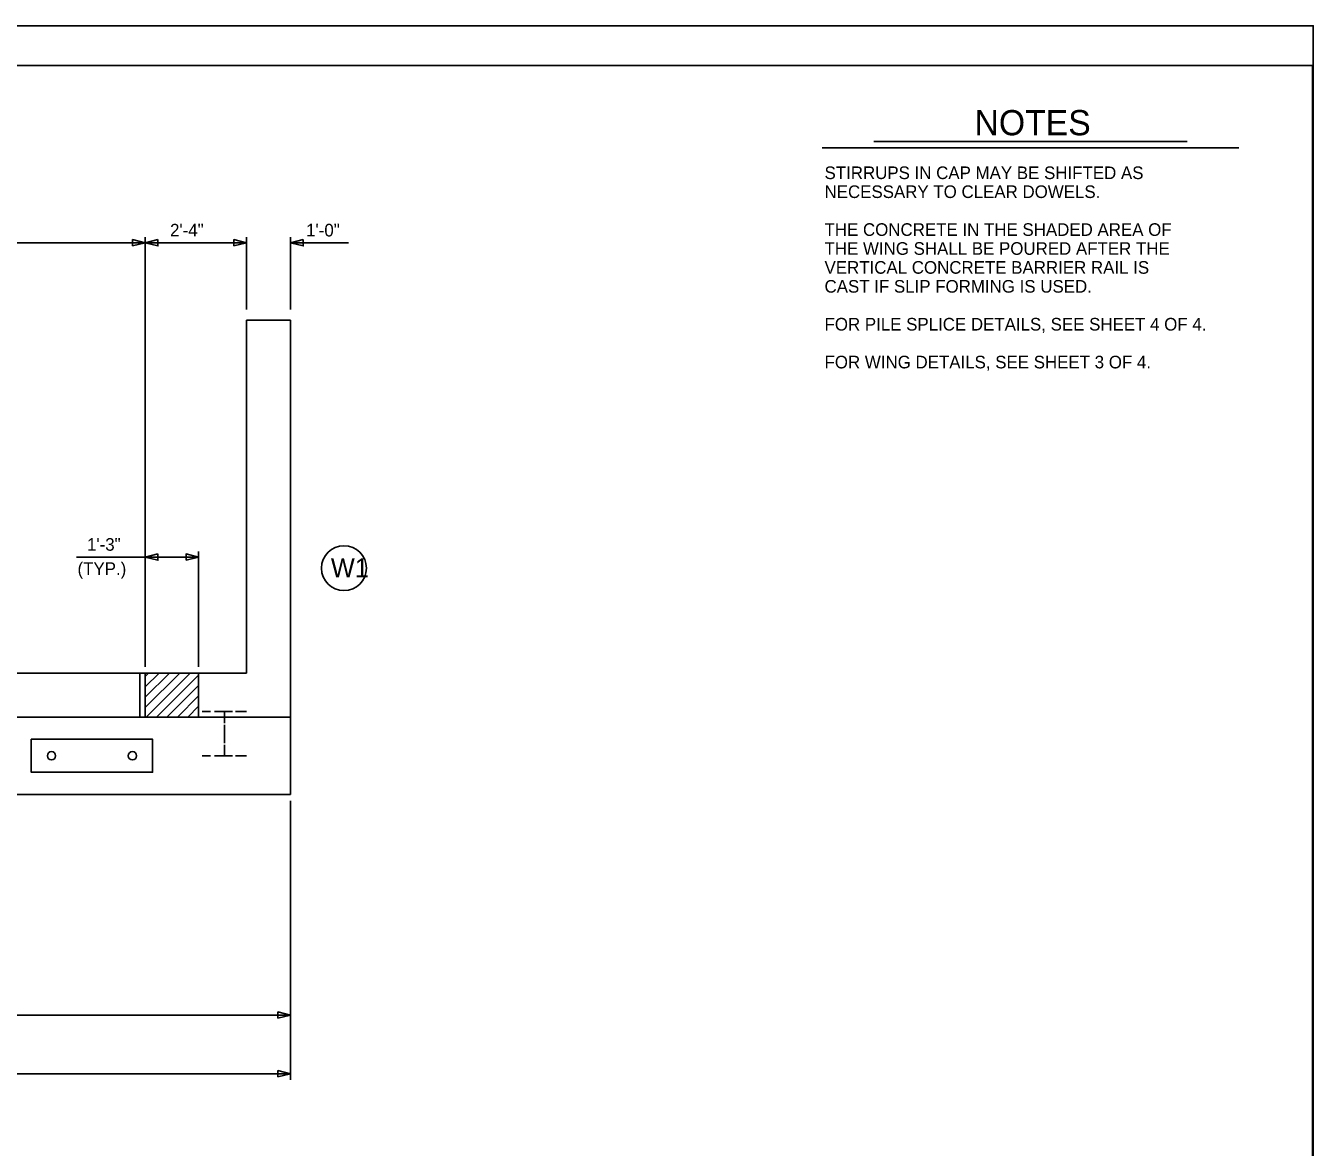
# Model space of a CAD drawing. Extents: x -41 to 251, y -169 to 237.
# Drawn here: x 132.26 to 161.43, y -25.59 to -0.17 of the extents above; entities that cross this region are included whole.
import ezdxf

# ---------------------------------------------------------------- set-up
doc = ezdxf.new("R2010")
doc.units = 0
for name, color, linetype in [('Arrowhead Terminators', 7, 'Continuous'), ('Dimension Lines', 7, 'Continuous'), ('Mis Object Lines', 7, 'Continuous'), ('Miscellaneous Lines', 7, 'Continuous'), ('Plan Sheet CELL', 7, 'Continuous'), ('Plot Shape CELL', 7, 'Continuous'), ('Rebar Lines', 7, 'Continuous'), ('Subtitle Text', 7, 'Continuous'), ('Text', 7, 'Continuous'), ('Title Text', 7, 'Continuous')]:
    doc.layers.add(name, color=color, linetype=linetype)

msp = doc.modelspace()

# ---------------------------------------------------------------- linework, layer by layer
at = {"layer": 'Arrowhead Terminators'}
for points in [[(134.685, -5.163), (134.971, -5.092), (134.685, -5.02)], [(135.257, -5.02), (134.971, -5.092), (135.257, -5.163)], [(136.977, -5.163), (137.263, -5.092), (136.977, -5.02)], [(138.549, -5.02), (138.263, -5.092), (138.549, -5.163)], [(135.257, -12.144), (134.971, -12.215), (135.257, -12.287)], [(135.894, -12.287), (136.18, -12.215), (135.894, -12.144)], [(137.977, -22.666), (138.263, -22.594), (137.977, -22.523)], [(137.977, -23.997), (138.263, -23.925), (137.977, -23.854)]]:
    msp.add_lwpolyline(points, close=True, dxfattribs=at)
at = {"layer": 'Dimension Lines'}
for p, q in [((118.763, -5.092), (134.971, -5.092)), ((134.971, -14.7), (134.971, -4.967)), ((134.971, -5.092), (137.263, -5.092)), ((137.263, -6.606), (137.263, -4.967)), ((138.263, -6.606), (138.263, -4.967)), ((139.575, -5.092), (138.263, -5.092)), ((133.416, -12.215), (134.971, -12.215)), ((134.971, -12.215), (136.18, -12.215)), ((136.18, -14.7), (136.18, -12.09)), ((134.846, -15.843), (134.846, -14.843)), ((134.846, -14.843), (134.971, -14.843)), ((134.971, -14.843), (134.971, -15.843)), ((134.971, -15.843), (134.846, -15.843)), ((138.263, -17.736), (138.263, -24.061)), ((118.763, -22.594), (138.263, -22.594)), ((99.263, -23.925), (138.263, -23.925))]:
    msp.add_line(p, q, dxfattribs=at)
msp.add_circle((139.472, -12.466), 0.509, dxfattribs=at)
at = {"layer": 'Mis Object Lines'}
for p, q in [((138.263, -6.843), (137.263, -6.843)), ((137.263, -6.843), (137.263, -14.843)), ((138.263, -15.843), (138.263, -6.843)), ((118.763, -14.843), (137.263, -14.843)), ((134.971, -14.843), (134.971, -15.843)), ((135.047, -14.843), (134.971, -14.919)), ((135.283, -14.843), (134.971, -15.155)), ((135.519, -14.843), (134.971, -15.391)), ((135.754, -14.843), (134.971, -15.626)), ((135.99, -14.843), (134.99, -15.843)), ((136.18, -14.843), (136.18, -15.843)), ((136.18, -14.89), (135.226, -15.843)), ((136.18, -15.125), (135.462, -15.843)), ((136.18, -15.361), (135.697, -15.843)), ((136.18, -15.597), (135.933, -15.843)), ((134.971, -15.843), (102.555, -15.843)), ((134.971, -15.843), (138.263, -15.843)), ((136.18, -15.832), (136.169, -15.843)), ((138.263, -17.593), (138.263, -15.843)), ((118.763, -17.593), (138.263, -17.593))]:
    msp.add_line(p, q, dxfattribs=at)
at = {"layer": 'Miscellaneous Lines'}
msp.add_lwpolyline([(132.388, -16.343), (135.138, -16.343), (135.138, -17.093), (132.388, -17.093)], close=True, dxfattribs=at)
at = {"layer": 'Plan Sheet CELL'}
for p, q in [((161.429, -0.174), (161.429, -0.174)), ((88.128, -1.076), (161.409, -1.076)), ((161.409, -1.076), (161.409, -49.166))]:
    msp.add_line(p, q, dxfattribs=at)
at = {"layer": 'Plot Shape CELL'}
msp.add_lwpolyline([(85.715, -0.174), (161.429, -0.174), (161.429, -50.554), (85.715, -50.554)], close=True, dxfattribs=at)
at = {"layer": 'Rebar Lines'}
for points in [[(136.261, -15.718), (136.452, -15.718)], [(136.539, -15.718), (136.947, -15.718)], [(136.763, -15.718), (136.763, -15.976)], [(137.018, -15.718), (137.261, -15.718)], [(136.763, -16.218), (136.763, -16.019)], [(136.763, -16.432), (136.763, -16.219)], [(136.763, -16.471), (136.763, -16.718)], [(136.261, -16.719), (136.452, -16.719)], [(136.539, -16.719), (136.947, -16.719)], [(137.018, -16.719), (137.261, -16.719)]]:
    msp.add_lwpolyline(points, dxfattribs=at)
for centre in [(132.846, -16.718), (134.68, -16.718)]:
    msp.add_circle(centre, 0.0938, dxfattribs=at)
at = {"layer": 'Title Text'}
for p, q in [((151.475, -2.799), (158.574, -2.799)), ((150.307, -2.942), (159.742, -2.942))]:
    msp.add_line(p, q, dxfattribs=at)

# ---------------------------------------------------------------- texts
at = {"layer": 'Subtitle Text'}
for s, height, p in [('STIRRUPS IN CAP MAY BE SHIFTED AS', 0.286, (150.358, -3.649)), ('NECESSARY TO CLEAR DOWELS.', 0.286, (150.358, -4.078)), ('THE CONCRETE IN THE SHADED AREA OF', 0.286, (150.358, -4.936)), ('THE WING SHALL BE POURED AFTER THE', 0.286, (150.358, -5.365)), ('VERTICAL CONCRETE BARRIER RAIL IS', 0.286, (150.358, -5.794)), ('CAST IF SLIP FORMING IS USED.', 0.286, (150.358, -6.223)), ('FOR PILE SPLICE DETAILS, SEE SHEET 4 OF 4.', 0.286, (150.358, -7.081)), ('FOR WING DETAILS, SEE SHEET 3 OF 4.', 0.286, (150.358, -7.939)), ('W1', 0.429, (139.175, -12.672))]:
    msp.add_text(s, height=height, dxfattribs=at).set_placement(p)
at = {"layer": 'Text'}
for s, p in [('2\'-4"', (135.532, -4.949)), ('1\'-0"', (138.614, -4.949)), ('1\'-3"', (133.651, -12.072)), ('(TYP.)', (133.436, -12.621))]:
    msp.add_text(s, height=0.286, dxfattribs=at).set_placement(p)
at = {"layer": 'Title Text'}
msp.add_text('NOTES', height=0.5714, dxfattribs=at).set_placement((153.756, -2.656))

doc.saveas('drawing.dxf')
